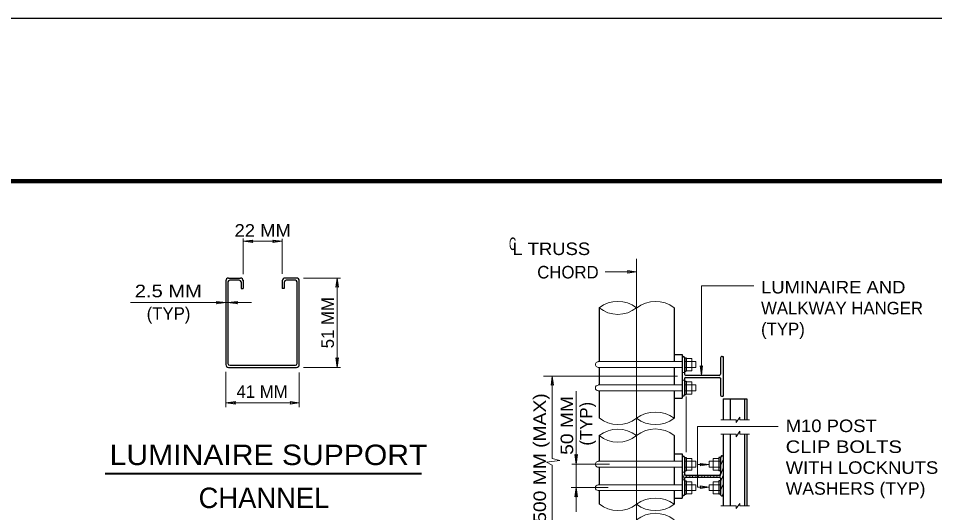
# Model space of a CAD drawing. Extents: x 312601.858 to 312602.699, y 144420.109 to 144420.704.
# Drawn here: x 312602.0438 to 312602.2633, y 144420.5851 to 144420.7035 of the extents above; entities that cross this region are included whole.
import ezdxf
from ezdxf.enums import TextEntityAlignment as Align

# ---------------------------------------------------------------- set-up
doc = ezdxf.new("R2010")
doc.units = 0
doc.header["$LTSCALE"] = 0.0012
doc.linetypes.add('DOT_DASHED', pattern=[7.7, 5, -1.2, 0.3, -1.2])
doc.linetypes.add('MEDIUM_DASHED', pattern=[4.5, 3, -1.5])
for name, color, linetype, lineweight in [('1', 7, 'Continuous', 13), ('2', 7, 'Continuous', 13), ('39', 7, 'Continuous', 13)]:
    doc.layers.add(name, color=color, linetype=linetype, lineweight=lineweight)

msp = doc.modelspace()

# ---------------------------------------------------------------- linework, layer by layer
at = {"layer": '1'}
for p, q in [((312602.0977, 144420.6508), (312602.0977, 144420.6422)), ((312602.0977, 144420.6504), (312602.0977, 144420.646)), ((312602.0977, 144420.6501), (312602.107, 144420.6501)), ((312602.107, 144420.6507), (312602.107, 144420.6423)), ((312602.121, 144420.6413), (312602.1121, 144420.6413)), ((312602.1202, 144420.6199), (312602.1202, 144420.6413)), ((312602.2074, 144420.6394), (312602.2074, 144420.618)), ((312602.22, 144420.6394), (312602.2074, 144420.6394)), ((312602.1827, 144420.6213), (312602.2009, 144420.6213)), ((312602.2051, 144420.6213), (312602.2061, 144420.6213)), ((312602.2061, 144420.6213), (312602.2061, 144420.6199)), ((312602.0935, 144420.6188), (312602.0935, 144420.6104)), ((312602.1111, 144420.6104), (312602.1111, 144420.6187)), ((312602.1121, 144420.6199), (312602.121, 144420.6199)), ((312602.2009, 144420.6199), (312602.1827, 144420.6199)), ((312602.2028, 144420.6187), (312602.2034, 144420.6187)), ((312602.2038, 144420.6191), (312602.2051, 144420.6191)), ((312602.2061, 144420.6199), (312602.2051, 144420.6199)), ((312602.2017, 144420.6178), (312602.1696, 144420.6178)), ((312602.1717, 144420.6178), (312602.1717, 144420.5981)), ((312602.2028, 144420.6168), (312602.2034, 144420.6168)), ((312602.2038, 144420.6164), (312602.2051, 144420.6164)), ((312602.2051, 144420.6135), (312602.2051, 144420.6164)), ((312602.2009, 144420.6157), (312602.1827, 144420.6157)), ((312602.1827, 144420.6143), (312602.2009, 144420.6143)), ((312602.2061, 144420.6157), (312602.2051, 144420.6157)), ((312602.2051, 144420.6143), (312602.2061, 144420.6143)), ((312602.2061, 144420.6143), (312602.2061, 144420.6157)), ((312602.2038, 144420.6135), (312602.2051, 144420.6135)), ((312602.2038, 144420.6129), (312602.2038, 144420.5996)), ((312602.0935, 144420.6114), (312602.1111, 144420.6114)), ((312602.2157, 144420.6067), (312602.2166, 144420.608)), ((312602.2166, 144420.6073), (312602.2166, 144420.608)), ((312602.2065, 144420.5912), (312602.2065, 144420.6057)), ((312602.2258, 144420.6057), (312602.2065, 144420.6057)), ((312602.2121, 144420.6073), (312602.2157, 144420.6073)), ((312602.2157, 144420.6067), (312602.2157, 144420.6073)), ((312602.2166, 144420.6073), (312602.2189, 144420.6073)), ((312602.2121, 144420.6039), (312602.2157, 144420.6039)), ((312602.2157, 144420.6033), (312602.2166, 144420.6046)), ((312602.2157, 144420.6033), (312602.2157, 144420.6039)), ((312602.2166, 144420.6039), (312602.2166, 144420.6046)), ((312602.2166, 144420.6039), (312602.2189, 144420.6039)), ((312602.2028, 144420.5992), (312602.2028, 144420.5902)), ((312602.1854, 144420.5967), (312602.1764, 144420.5967)), ((312602.1827, 144420.5974), (312602.2009, 144420.5974)), ((312602.2051, 144420.5974), (312602.2061, 144420.5974)), ((312602.2061, 144420.5974), (312602.2061, 144420.596)), ((312602.2093, 144420.5974), (312602.2093, 144420.596)), ((312602.2102, 144420.5974), (312602.2093, 144420.5974)), ((312602.2116, 144420.5981), (312602.2102, 144420.5981)), ((312602.2102, 144420.5981), (312602.2102, 144420.5953)), ((312602.212, 144420.598), (312602.2123, 144420.5987)), ((312602.212, 144420.5963), (312602.2126, 144420.5978)), ((312602.2009, 144420.596), (312602.1827, 144420.596)), ((312602.2028, 144420.5948), (312602.2034, 144420.5948)), ((312602.2038, 144420.5953), (312602.2051, 144420.5953)), ((312602.2061, 144420.596), (312602.2051, 144420.596)), ((312602.2093, 144420.5966), (312602.2065, 144420.5966)), ((312602.2093, 144420.596), (312602.2102, 144420.596)), ((312602.2116, 144420.5953), (312602.2102, 144420.5953)), ((312602.2118, 144420.5936), (312602.2126, 144420.5958)), ((312602.2028, 144420.593), (312602.2034, 144420.593)), ((312602.2029, 144420.593), (312602.2034, 144420.5944)), ((312602.2038, 144420.5936), (312602.204, 144420.5941)), ((312602.2038, 144420.5925), (312602.2051, 144420.5925)), ((312602.2046, 144420.5936), (312602.2047, 144420.5941)), ((312602.2051, 144420.5896), (312602.2051, 144420.5925)), ((312602.2052, 144420.5936), (312602.2054, 144420.5941)), ((312602.206, 144420.5936), (312602.2062, 144420.5941)), ((312602.2067, 144420.5936), (312602.2068, 144420.5941)), ((312602.2074, 144420.5936), (312602.2076, 144420.5941)), ((312602.2081, 144420.5936), (312602.2083, 144420.5941)), ((312602.2089, 144420.5936), (312602.2091, 144420.5941)), ((312602.2096, 144420.5936), (312602.2097, 144420.5941)), ((312602.2116, 144420.5925), (312602.2102, 144420.5925)), ((312602.2103, 144420.5936), (312602.2105, 144420.5941)), ((312602.211, 144420.5936), (312602.2113, 144420.5941)), ((312602.212, 144420.5925), (312602.2126, 144420.5941)), ((312602.1851, 144420.5911), (312602.1762, 144420.5911)), ((312602.2009, 144420.5918), (312602.1827, 144420.5918)), ((312602.1827, 144420.5904), (312602.2009, 144420.5904)), ((312602.2061, 144420.5918), (312602.2051, 144420.5918)), ((312602.2051, 144420.5904), (312602.2061, 144420.5904)), ((312602.2061, 144420.5904), (312602.2061, 144420.5918)), ((312602.2065, 144420.5912), (312602.2093, 144420.5912)), ((312602.2093, 144420.5904), (312602.2093, 144420.5918)), ((312602.2093, 144420.5918), (312602.2102, 144420.5918)), ((312602.2102, 144420.5904), (312602.2093, 144420.5904)), ((312602.212, 144420.5904), (312602.2126, 144420.5919)), ((312602.2038, 144420.5896), (312602.2051, 144420.5896)), ((312602.2124, 144420.5891), (312602.2126, 144420.5898)), ((312602.2121, 144420.5867), (312602.2157, 144420.5867)), ((312602.2157, 144420.5861), (312602.2166, 144420.5873)), ((312602.2157, 144420.5861), (312602.2157, 144420.5867)), ((312602.2166, 144420.5867), (312602.2166, 144420.5873)), ((312602.2166, 144420.5867), (312602.2189, 144420.5867))]:
    msp.add_line(p, q, dxfattribs=at)
at = {"layer": '1', "lineweight": 25}
for p, q in [((312602.0935, 144420.6406), (312602.0935, 144420.6206)), ((312602.0942, 144420.6413), (312602.097, 144420.6413)), ((312602.0967, 144420.6408), (312602.0945, 144420.6408)), ((312602.0977, 144420.6408), (312602.0977, 144420.6388)), ((312602.0977, 144420.6406), (312602.0977, 144420.6388)), ((312602.107, 144420.6407), (312602.107, 144420.6388)), ((312602.107, 144420.6406), (312602.107, 144420.6388)), ((312602.1104, 144420.6413), (312602.1077, 144420.6413)), ((312602.1102, 144420.6408), (312602.108, 144420.6408)), ((312602.1111, 144420.6206), (312602.1111, 144420.6406)), ((312602.094, 144420.6404), (312602.094, 144420.6208)), ((312602.0972, 144420.6404), (312602.0972, 144420.6388)), ((312602.0972, 144420.6388), (312602.0977, 144420.6388)), ((312602.1075, 144420.6388), (312602.107, 144420.6388)), ((312602.1075, 144420.6404), (312602.1075, 144420.6388)), ((312602.1106, 144420.6208), (312602.1106, 144420.6404)), ((312602.1829, 144420.6342), (312602.1829, 144420.6213)), ((312602.2009, 144420.6342), (312602.2009, 144420.6213)), ((312602.2028, 144420.623), (312602.2028, 144420.6141)), ((312602.2028, 144420.6225), (312602.2031, 144420.6225)), ((312602.2034, 144420.6222), (312602.2034, 144420.6183)), ((312602.2034, 144420.6222), (312602.2038, 144420.6222)), ((312602.2038, 144420.6222), (312602.2038, 144420.619)), ((312602.212, 144420.6222), (312602.212, 144420.6183)), ((312602.2124, 144420.6225), (312602.2126, 144420.6225)), ((312602.2126, 144420.6225), (312602.2126, 144420.613)), ((312602.0942, 144420.6199), (312602.1104, 144420.6199)), ((312602.0945, 144420.6204), (312602.1102, 144420.6204)), ((312602.1829, 144420.6199), (312602.1829, 144420.6157)), ((312602.2009, 144420.6199), (312602.2009, 144420.6157)), ((312602.2034, 144420.619), (312602.2038, 144420.619)), ((312602.2034, 144420.6173), (312602.2034, 144420.6134)), ((312602.2034, 144420.6166), (312602.2038, 144420.6166)), ((312602.2036, 144420.618), (312602.2118, 144420.618)), ((312602.2036, 144420.6175), (312602.2118, 144420.6175)), ((312602.2038, 144420.6166), (312602.2038, 144420.6134)), ((312602.212, 144420.6173), (312602.212, 144420.6134)), ((312602.1829, 144420.6143), (312602.1829, 144420.6078)), ((312602.2009, 144420.6143), (312602.2009, 144420.6077)), ((312602.2009, 144420.6125), (312602.2028, 144420.6125)), ((312602.2028, 144420.6131), (312602.2031, 144420.6131)), ((312602.2034, 144420.6134), (312602.2038, 144420.6134)), ((312602.2124, 144420.613), (312602.2126, 144420.613)), ((312602.2126, 144420.6124), (312602.2183, 144420.6124)), ((312602.2126, 144420.6124), (312602.2126, 144420.6073)), ((312602.2143, 144420.6124), (312602.2143, 144420.6073)), ((312602.2177, 144420.6124), (312602.2177, 144420.6073)), ((312602.2183, 144420.6124), (312602.2183, 144420.6073)), ((312602.1829, 144420.6036), (312602.1829, 144420.5974)), ((312602.2009, 144420.6036), (312602.2009, 144420.5974)), ((312602.2126, 144420.6039), (312602.2126, 144420.5867)), ((312602.2143, 144420.6039), (312602.2143, 144420.5867)), ((312602.2177, 144420.6039), (312602.2177, 144420.5867)), ((312602.2183, 144420.6039), (312602.2183, 144420.5867)), ((312602.2028, 144420.5986), (312602.2031, 144420.5986)), ((312602.2034, 144420.5983), (312602.2034, 144420.5944)), ((312602.2034, 144420.5983), (312602.2038, 144420.5983)), ((312602.2038, 144420.5983), (312602.2038, 144420.5951)), ((312602.2116, 144420.5983), (312602.2116, 144420.5951)), ((312602.212, 144420.5983), (312602.2116, 144420.5983)), ((312602.212, 144420.5983), (312602.212, 144420.5944)), ((312602.2124, 144420.5987), (312602.2126, 144420.5987)), ((312602.1829, 144420.596), (312602.1829, 144420.5918)), ((312602.2009, 144420.596), (312602.2009, 144420.5918)), ((312602.2034, 144420.5951), (312602.2038, 144420.5951)), ((312602.212, 144420.5951), (312602.2116, 144420.5951)), ((312602.2034, 144420.5934), (312602.2034, 144420.5895)), ((312602.2034, 144420.5927), (312602.2038, 144420.5927)), ((312602.2036, 144420.5941), (312602.2118, 144420.5941)), ((312602.2036, 144420.5936), (312602.2118, 144420.5936)), ((312602.2038, 144420.5927), (312602.2038, 144420.5895)), ((312602.212, 144420.5927), (312602.2116, 144420.5927)), ((312602.2116, 144420.5927), (312602.2116, 144420.5895)), ((312602.212, 144420.5934), (312602.212, 144420.5895)), ((312602.1829, 144420.5904), (312602.1829, 144420.5872)), ((312602.2009, 144420.5904), (312602.2009, 144420.5871)), ((312602.2009, 144420.5886), (312602.2028, 144420.5886)), ((312602.2028, 144420.5892), (312602.2031, 144420.5892)), ((312602.2034, 144420.5895), (312602.2038, 144420.5895)), ((312602.212, 144420.5895), (312602.2116, 144420.5895)), ((312602.2124, 144420.5891), (312602.2126, 144420.5891))]:
    msp.add_line(p, q, dxfattribs=at)
at = {"layer": '1', "linetype": 'MEDIUM_DASHED'}
for p, q in [((312602.2009, 144420.6213), (312602.2028, 144420.6213)), ((312602.2034, 144420.6213), (312602.2051, 144420.6213)), ((312602.2028, 144420.6199), (312602.2009, 144420.6199)), ((312602.2051, 144420.6199), (312602.2034, 144420.6199)), ((312602.2028, 144420.6157), (312602.2009, 144420.6157)), ((312602.2009, 144420.6143), (312602.2028, 144420.6143)), ((312602.2051, 144420.6157), (312602.2034, 144420.6157)), ((312602.2034, 144420.6143), (312602.2051, 144420.6143)), ((312602.2009, 144420.5974), (312602.2028, 144420.5974)), ((312602.2034, 144420.5974), (312602.2051, 144420.5974)), ((312602.212, 144420.5974), (312602.2102, 144420.5974)), ((312602.2028, 144420.596), (312602.2009, 144420.596)), ((312602.2051, 144420.596), (312602.2034, 144420.596)), ((312602.2102, 144420.596), (312602.212, 144420.596)), ((312602.2028, 144420.5918), (312602.2009, 144420.5918)), ((312602.2009, 144420.5904), (312602.2028, 144420.5904)), ((312602.2051, 144420.5918), (312602.2034, 144420.5918)), ((312602.2034, 144420.5904), (312602.2051, 144420.5904)), ((312602.2102, 144420.5918), (312602.212, 144420.5918)), ((312602.212, 144420.5904), (312602.2102, 144420.5904))]:
    msp.add_line(p, q, dxfattribs=at)
at = {"layer": '1'}
for points in [[(312602.1, 144420.6498), (312602.0977, 144420.6501), (312602.1, 144420.6504), (312602.0997, 144420.6501)], [(312602.1048, 144420.6504), (312602.107, 144420.6501), (312602.1048, 144420.6498), (312602.105, 144420.6501)], [(312602.1897, 144420.6431), (312602.1919, 144420.6428), (312602.1897, 144420.6425), (312602.1899, 144420.6428)], [(312602.1199, 144420.6391), (312602.1202, 144420.6413), (312602.1205, 144420.6391), (312602.1202, 144420.6393)], [(312602.0913, 144420.6357), (312602.0935, 144420.6354), (312602.0913, 144420.6351), (312602.0915, 144420.6354)], [(312602.0963, 144420.6351), (312602.094, 144420.6354), (312602.0963, 144420.6357), (312602.096, 144420.6354)], [(312602.1205, 144420.6222), (312602.1202, 144420.6199), (312602.1199, 144420.6222), (312602.1202, 144420.6219)], [(312602.2077, 144420.6203), (312602.2074, 144420.618), (312602.2071, 144420.6203), (312602.2074, 144420.62)], [(312602.1714, 144420.6156), (312602.1717, 144420.6178), (312602.172, 144420.6156), (312602.1717, 144420.6158)], [(312602.0958, 144420.6111), (312602.0935, 144420.6114), (312602.0958, 144420.6117), (312602.0955, 144420.6114)], [(312602.1089, 144420.6117), (312602.1111, 144420.6114), (312602.1089, 144420.6111), (312602.1091, 144420.6114)], [(312602.1777, 144420.599), (312602.1774, 144420.5967), (312602.1771, 144420.599), (312602.1774, 144420.5987)], [(312602.2071, 144420.5969), (312602.2093, 144420.5966), (312602.2071, 144420.5963), (312602.2073, 144420.5966)], [(312602.1771, 144420.5889), (312602.1774, 144420.5911), (312602.1777, 144420.5889), (312602.1774, 144420.5891)], [(312602.2071, 144420.5915), (312602.2093, 144420.5912), (312602.2071, 144420.5909), (312602.2073, 144420.5912)]]:
    msp.add_lwpolyline(points, close=True, dxfattribs=at)
for points in [[(312602.0707, 144420.6354), (312602.0935, 144420.6354), (312602.094, 144420.6354), (312602.0997, 144420.6354)], [(312602.2038, 144420.622), (312602.2051, 144420.622), (312602.2051, 144420.6191)], [(312602.1774, 144420.6142), (312602.1774, 144420.5967), (312602.1774, 144420.5911), (312602.1774, 144420.5853)], [(312602.2038, 144420.5981), (312602.2051, 144420.5981), (312602.2051, 144420.5953)], [(312602.1717, 144420.5965), (312602.1717, 144420.5772), (312602.1717, 144420.5579)], [(312602.2116, 144420.5896), (312602.2102, 144420.5896), (312602.2102, 144420.5925)]]:
    msp.add_lwpolyline(points, dxfattribs=at)
at = {"layer": '1', "lineweight": 25}
for points in [[(312602.2009, 144420.623), (312602.2028, 144420.623), (312602.2028, 144420.6125)], [(312602.2009, 144420.5992), (312602.2028, 144420.5992), (312602.2028, 144420.5886)]]:
    msp.add_lwpolyline(points, dxfattribs=at)
for centre, radius, start, end in [((312602.094195, 144420.64062), 0.00068, 90, 180), ((312602.09445, 144420.640365), 0.000425, 90, 180), ((312602.096745, 144420.640365), 0.000425, 0, 90), ((312602.097, 144420.64062), 0.00068, 0, 90), ((312602.10771, 144420.64062), 0.00068, 90, 180), ((312602.107965, 144420.640365), 0.000425, 90, 180), ((312602.110175, 144420.640365), 0.000425, 0, 90), ((312602.11043, 144420.64062), 0.00068, 0, 89.99844), ((312602.09445, 144420.620815), 0.000425, 180, 270), ((312602.110175, 144420.620815), 0.000425, 270.00156, 0), ((312602.094195, 144420.62056), 0.00068, 180, 270), ((312602.11043, 144420.62056), 0.00068, 270.00156, 359.99844), ((312602.21237, 144420.58947), 0.00037, 175.73894, 275.04245)]:
    msp.add_arc(centre, radius, start, end, dxfattribs=at)
at = {"layer": '1'}
for centre, radius, start, end in [((312602.1874, 144420.6282), 0.0075, 53.1301, 126.8699), ((312602.1874, 144420.639725), 0.007126, 230.83789, 309.16211), ((312602.196464, 144420.628399), 0.007303, 52.59302, 128.67006), ((312602.182705, 144420.62058), 0.00068, 89.99844, 269.99844), ((312602.182705, 144420.61497), 0.00068, 90.00156, 270), ((312602.187464, 144420.613509), 0.007309, 231.35969, 307.36712), ((312602.1964, 144420.601703), 0.007497, 53.11482, 126.88518), ((312602.1964, 144420.613697), 0.007497, 233.11482, 306.88518), ((312602.1874, 144420.5976), 0.0075, 53.1301, 126.8699), ((312602.1874, 144420.5976), 0.0075, 53.1301, 126.8699), ((312602.1874, 144420.5976), 0.0075, 53.1301, 126.8699), ((312602.1874, 144420.609125), 0.007126, 230.83789, 309.16211), ((312602.1874, 144420.609125), 0.007126, 230.83789, 309.16211), ((312602.1874, 144420.609125), 0.007126, 230.83789, 309.16211), ((312602.182705, 144420.596695), 0.00068, 89.99844, 269.99844), ((312602.182705, 144420.591085), 0.00068, 90.00156, 270), ((312602.1964, 144420.581103), 0.007497, 53.11482, 126.88518), ((312602.187464, 144420.592909), 0.007309, 231.35969, 307.36712), ((312602.1964, 144420.593097), 0.007497, 233.11482, 306.88518)]:
    msp.add_arc(centre, radius, start, end, dxfattribs=at)
at = {"layer": '1', "lineweight": 25}
for centre, major_axis, ratio, start_param, end_param in [((312602.203105, 144420.622195), (0, 0.000305), 0.967213, 4.712389, 6.2831853), ((312602.21237, 144420.622195), (-0.00037, 0), 0.824324, 4.6314849, 6.2831853), ((312602.203615, 144420.618285), (0, -0.000285), 0.754386, 4.712389, 6.2831853), ((312602.203615, 144420.617265), (0, -0.000235), 0.914894, 3.1415927, 4.712389), ((312602.211775, 144420.618285), (0, -0.000285), 0.789474, 6.2831853, 7.8539816), ((312602.211775, 144420.617265), (0, 0.000235), 0.957447, 4.712389, 6.2831853), ((312602.203105, 144420.613355), (0.000295, 0), 0.864407, 4.712389, 6.4578575), ((312602.21237, 144420.613355), (-0.00037, 0), 0.959459, 6.1570972, 7.9348857), ((312602.203105, 144420.59831), (0.000295, 0), 0.983051, 6.2831853, 7.8539816), ((312602.21237, 144420.59831), (0, -0.00039), 0.948718, 3.0606885, 4.712389), ((312602.203615, 144420.5944), (0, -0.0003), 0.716667, 4.712389, 6.2831853), ((312602.203615, 144420.59338), (0, -0.00022), 0.977273, 3.1415927, 4.712389), ((312602.211775, 144420.5944), (0, -0.0003), 0.75, 6.2831853, 7.8539816), ((312602.211775, 144420.59338), (-0.000225, 0), 0.977778, 3.1415927, 4.712389), ((312602.203105, 144420.58947), (0.000295, 0), 0.864407, 4.712389, 6.400294)]:
    msp.add_ellipse(centre, major_axis=major_axis, ratio=ratio, start_param=start_param, end_param=end_param, dxfattribs=at)
at = {"layer": '1'}
for centre in [(312602.196464, 144420.597799), (312602.196464, 144420.597799), (312602.196464, 144420.577599)]:
    msp.add_ellipse(centre, major_axis=(-0.004613, 0.005762), ratio=0.989423, start_param=4.9552139, end_param=6.2831853, dxfattribs=at)
at = {"layer": '2', "linetype": 'DOT_DASHED'}
msp.add_line((312602.1919, 144420.6459), (312602.1919, 144420.4762), dxfattribs=at)
at = {"layer": '2'}
msp.add_line((312602.1844, 144420.6428), (312602.1919, 144420.6428), dxfattribs=at)
at = {"layer": '2', "lineweight": 40}
msp.add_line((312602.0646, 144420.5945), (312602.1404, 144420.5945), dxfattribs=at)
at = {"layer": '2'}
msp.add_lwpolyline([(312602.1717, 144420.5965), (312602.1703, 144420.5972), (312602.1735, 144420.5976), (312602.1717, 144420.5981)], dxfattribs=at)
at = {"layer": '39', "lineweight": 25}
msp.add_line((312601.8578, 144420.7035), (312602.6988, 144420.7035), dxfattribs=at)
at = {"layer": '39', "lineweight": 158}
msp.add_lwpolyline([(312601.9088, 144420.1247), (312601.9088, 144420.6645), (312602.6838, 144420.6645)], dxfattribs=at)

# ---------------------------------------------------------------- texts
at = {"layer": '1'}
for s, width, p in [('C', 0.6, (312602.1622, 144420.648)), ('L TRUSS', 1.1, (312602.17145, 144420.6468))]:
    msp.add_text(s, height=0.003, dxfattribs=dict(at, width=width)).set_placement(p, align=Align.CENTER)
at = {"layer": '2'}
for s, width, p in [('22 MM', 1.1, (312602.10235, 144420.6512)), ('2.5 MM', 1.2, (312602.07975, 144420.6367))]:
    msp.add_text(s, height=0.003, dxfattribs=dict(at, width=width)).set_placement(p, align=Align.CENTER)
for s, p in [('CHORD', (312602.17545, 144420.6412)), ('(TYP)', (312602.0798, 144420.6313)), ('41 MM', (312602.1022, 144420.6126))]:
    msp.add_text(s, height=0.003, dxfattribs=at).set_placement(p, align=Align.CENTER)
for s, height, width, p in [('LUMINAIRE AND', 0.003, 1.1, (312602.2217, 144420.6376)), ('M10 POST', 0.003, 1.1, (312602.2276, 144420.6044)), ('LUMINAIRE SUPPORT', 0.0049, 1.1, (312602.0657, 144420.5965)), ('CLIP BOLTS ', 0.003, 1.2, (312602.2276, 144420.5994)), ('WITH LOCKNUTS AND', 0.003, 1.1, (312602.2276, 144420.5944)), ('WASHERS (TYP)', 0.003, 1.05, (312602.2276, 144420.5894))]:
    msp.add_text(s, height=height, dxfattribs=dict(at, width=width)).set_placement(p)
for s, p in [('51 MM', (312602.1194, 144420.6306)), ('(TYP)', (312602.1813, 144420.6064))]:
    msp.add_text(s, height=0.003, rotation=90, dxfattribs=at).set_placement(p, align=Align.CENTER)
for s, height, p in [('WALKWAY HANGER', 0.003, (312602.2217, 144420.6326)), ('(TYP)', 0.003, (312602.2217, 144420.6276)), ('CHANNEL', 0.0049, (312602.087, 144420.5862))]:
    msp.add_text(s, height=height, dxfattribs=at).set_placement(p)
at = {"layer": '2', "width": 1.15}
for s, p in [('1500 MM (MAX)', (312602.1702, 144420.5969)), ('50 MM', (312602.1767, 144420.606))]:
    msp.add_text(s, height=0.003, rotation=90, dxfattribs=at).set_placement(p, align=Align.CENTER)

doc.saveas('drawing.dxf')
